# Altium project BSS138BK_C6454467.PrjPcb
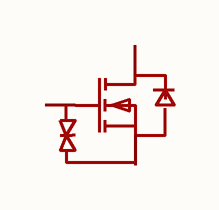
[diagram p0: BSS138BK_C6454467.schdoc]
1 sheet, 1 parts. Net scope: global (net labels, ports and power ports of the same name join across sheets).

## Sheet BSS138BK_C6454467.schdoc
size 127 x 101 mm

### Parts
Q?  bss138bk_c6454467  [SOT-23-3_L2.9-W1.3-P1.90-LS2.4-BR]  (value not drawn)

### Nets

Not connected (* = marked no-connect by the designer): Q? 1(G) 2(S) 3(D)

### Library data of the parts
Q? = bss138bk_c6454467: 数量:1个N沟道;漏源电压(Vdss):55V;连续漏极电流(Id):300mA;导通电阻(RDS(on)):1.2Ω@10V;耗散功率(Pd):350mW;阈值电压(Vgs(th)):1.1V;; Manufacturer: MSKSEMI(美森科); AddInBom: yes; ModelId: c62791f0466c4ae2a892c056b845b0ca; ModelName: SOT-23-3P_L2.9-W1.3-H1.0-LS2.4-P0.95; ModelTransform: 98.425,114.173,0,180,0,0,0.0005,-0.0005,0; Number: 1个N沟道; Drain to Source Voltage: 55V; Current - Continuous Drain(Id): 300mA; Pd - Power Dissipation: 350mW; Gate Threshold Voltage (Vgs(th)): 1.1V; Gate Charge(Qg): 3.7nC@10V; Input Capacitance(Ciss): 25.5pF; Reverse Transfer Capacitance (Crss@Vds): 7.8pF; Type: N沟道; Output Capacitance(Coss): 17pF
